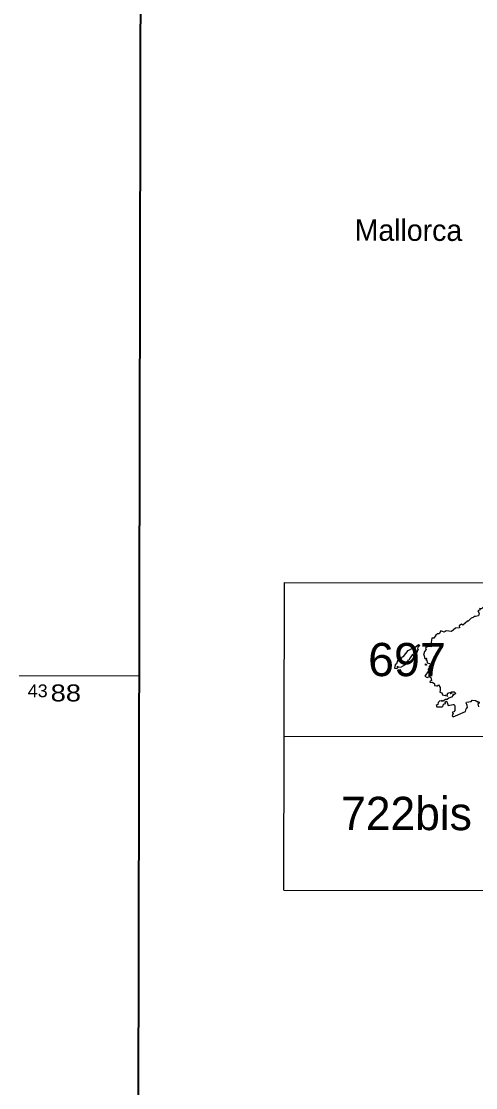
# Model space of a CAD drawing. Extents: x 483840 to 488445, y 4386047 to 4389027.
# Drawn here: x 487686 to 487953, y 4387758 to 4388384 of the extents above; entities that cross this region are included whole.
import ezdxf
from ezdxf.enums import TextEntityAlignment as Align

# ---------------------------------------------------------------- set-up
doc = ezdxf.new("R2010")
doc.units = 0
doc.header["$LTSCALE"] = 4
doc.linetypes.add('DOTTED', pattern=[1.5, 0.3, -1.2])
for name, color, linetype, lineweight in [('1', 7, 'Continuous', 13), ('2', 7, 'DOTTED', 13), ('3', 7, 'Continuous', 25)]:
    doc.layers.add(name, color=color, linetype=linetype, lineweight=lineweight)

msp = doc.modelspace()

# ---------------------------------------------------------------- linework, layer by layer
at = {"layer": '1', "lineweight": 25}
for p, q in [((487840.05, 4387874.26), (487840.4, 4388054.9)), ((487840.39, 4388054.9), (488394.63, 4388053.84)), ((487840.22, 4387964.58), (488394.46, 4387963.51)), ((487840.04, 4387874.26), (488394.28, 4387873.19))]:
    msp.add_line(p, q, dxfattribs=at)
at = {"layer": '1'}
msp.add_line((487684.53, 4388000), (487754.91, 4388000), dxfattribs=at)
at = {"layer": '1', "lineweight": 35}
msp.add_lwpolyline([(484040.1, 4388831.88), (487756.5, 4388824.71), (487751.76, 4386369.72), (484035.36, 4386376.89)], close=True, dxfattribs=at)
at = {"layer": '3'}
for points in [[(487960.73, 4388042.23), (487960.22, 4388042.52), (487958.39, 4388041.46), (487956.12, 4388039.38), (487955.03, 4388039.6), (487955.28, 4388038.81), (487954.1, 4388038.28), (487954.75, 4388036.84), (487954.39, 4388035.2), (487952.69, 4388034.85)], [(487952.69, 4388034.85), (487951.84, 4388034.93), (487951.24, 4388034.21), (487950.13, 4388033.95), (487948.34, 4388032.08), (487947.92, 4388032.11), (487945.14, 4388029.8), (487944.5, 4388030.36), (487943.06, 4388029.39), (487943.26, 4388028.19), (487940.94, 4388028.1), (487938.45, 4388026.04)], [(487938.45, 4388026.04), (487935.45, 4388026.54), (487934.22, 4388025.63), (487932.26, 4388026.54), (487931.32, 4388024.78), (487930.22, 4388024.69), (487929.34, 4388023.93), (487928.23, 4388022.1), (487926.94, 4388022.09), (487926.65, 4388019.87), (487926.92, 4388018.79), (487926.36, 4388017.78), (487926.49, 4388017.05), (487924.41, 4388017.19)], [(487909.25, 4388010.64), (487909.77, 4388011.4), (487910.33, 4388011.42), (487913.02, 4388014.97), (487916, 4388016.51), (487917.07, 4388016.71), (487919.08, 4388018.37), (487919.84, 4388017.94), (487918.79, 4388016.83), (487918.5, 4388015.74), (487919, 4388015.7), (487917.7, 4388013.05), (487917.04, 4388012.99), (487916.82, 4388012.41), (487915.86, 4388011.91), (487915.75, 4388012.51), (487915.37, 4388012.44), (487914.33, 4388010.59)], [(487924.41, 4388017.19), (487923.19, 4388016.28), (487923.56, 4388015.54), (487922.74, 4388014.36), (487922.14, 4388012.18), (487922.45, 4388012.02), (487922.66, 4388010.52)], [(487909.25, 4388010.64), (487906.84, 4388008.83), (487906.23, 4388007.08), (487905.46, 4388006.48), (487905.05, 4388004.52), (487906.13, 4388004.25), (487906.76, 4388004.54), (487906.8, 4388005.69), (487907.43, 4388005.06), (487909.21, 4388005.32)], [(487914.33, 4388010.59), (487913.4, 4388009.18), (487912.59, 4388008.98), (487912.96, 4388008.58), (487911.69, 4388007.58), (487911.33, 4388006.58), (487909.21, 4388005.32)], [(487922.66, 4388010.52), (487922.93, 4388010.23), (487923.81, 4388010.5), (487923.51, 4388009.45), (487924.03, 4388009.42), (487924.22, 4388007.75), (487925.71, 4388007.22), (487926.2, 4388006.42), (487925.32, 4388005.54), (487925.4, 4388004.71), (487925.68, 4388004.73), (487924.89, 4388004.05), (487925.06, 4388003.02), (487922.8, 4387999.94), (487924.15, 4387998.98), (487925.6, 4387999.66)], [(487925.6, 4387999.66), (487926.45, 4387999.06), (487926.78, 4387997.37), (487925.84, 4387996.42), (487925.94, 4387996.1), (487927.13, 4387996.24), (487928.09, 4387995.81), (487928.59, 4387995.37), (487928.52, 4387994.29), (487929.86, 4387994.09), (487929.89, 4387993.8), (487930.84, 4387994.68), (487931.88, 4387993.28), (487931.89, 4387991.36)], [(487938.47, 4387990.56), (487940.02, 4387990.66), (487940.98, 4387989.59), (487939.82, 4387988.81), (487939.23, 4387989.21), (487939.55, 4387988.64), (487938.56, 4387987.47), (487937.04, 4387986.95), (487936.08, 4387986.12), (487935.1, 4387986.05), (487933.24, 4387985.03), (487933, 4387985.62), (487932.39, 4387985.25), (487931.61, 4387985.35), (487930.71, 4387984.29), (487930.47, 4387983.24)], [(487931.89, 4387991.36), (487931.68, 4387990.43), (487932.88, 4387989.97), (487933.23, 4387988.93), (487934.72, 4387988.59), (487935.37, 4387988.97), (487936.22, 4387987.98), (487935.96, 4387988.64), (487936.28, 4387989.79), (487937.59, 4387990.2), (487938.27, 4387989.44), (487937.69, 4387990.21), (487938.02, 4387989.82), (487937.97, 4387990.28), (487938.33, 4387990.07), (487938.38, 4387990.43), (487938.52, 4387989.74), (487938.47, 4387990.56)], [(487930.47, 4387983.24), (487929.52, 4387982.68), (487929.83, 4387981.85), (487933.08, 4387981.84), (487933.71, 4387982.45), (487933.81, 4387983.4), (487935.06, 4387983.81), (487934.86, 4387984.73), (487935.37, 4387985.09), (487936.04, 4387984.42), (487936.52, 4387982.6), (487939.55, 4387983.21), (487940.03, 4387983.18), (487940.49, 4387982.4)], [(487940.49, 4387982.4), (487940.43, 4387979.75), (487939.93, 4387978.87), (487939.12, 4387978.68), (487939.04, 4387978.06), (487939.45, 4387977.86), (487938.91, 4387976.62), (487939.58, 4387976), (487946.84, 4387979.09), (487947.16, 4387980.64), (487947.62, 4387981), (487947.58, 4387981.54), (487947.93, 4387981.48), (487947.74, 4387982.65)], [(487947.74, 4387982.65), (487947.17, 4387984.21), (487947.42, 4387984.65), (487950, 4387984.88), (487950.62, 4387985.77), (487952.62, 4387985.63), (487953.17, 4387985.11), (487953.47, 4387985.27), (487953.54, 4387984.71), (487954.24, 4387985.02), (487954.27, 4387984.34), (487954.45, 4387984.87), (487954.81, 4387984.67), (487954.73, 4387984.05), (487954.02, 4387983.53), (487954.36, 4387981.86)]]:
    msp.add_lwpolyline(points, dxfattribs=at)
msp.add_lwpolyline([(487923.73, 4388006.86), (487923.82, 4388006.25), (487923.23, 4388006.29), (487923.24, 4388007.04)], close=True, dxfattribs=at)

# ---------------------------------------------------------------- texts
at = {"layer": '2'}
msp.add_text('Mallorca', height=12.5, rotation=359.889, dxfattribs=at).set_placement((487881.64, 4388255.49))
at = {"layer": '2', "width": 1.05}
msp.add_text('697', height=19.5, rotation=359.889, dxfattribs=at).set_placement((487912.33, 4387999.83), align=Align.CENTER)
at = {"layer": '2'}
for s, height, width, p in [('43', 7.5, 1.05, (487689.52, 4387987.5)), ('88  ', 10, 1.2, (487702.97, 4387985))]:
    msp.add_text(s, height=height, dxfattribs=dict(at, width=width)).set_placement(p)
msp.add_text('722bis', height=19.5, rotation=359.889, dxfattribs=at).set_placement((487912.08, 4387909.5), align=Align.CENTER)

doc.saveas('drawing.dxf')
